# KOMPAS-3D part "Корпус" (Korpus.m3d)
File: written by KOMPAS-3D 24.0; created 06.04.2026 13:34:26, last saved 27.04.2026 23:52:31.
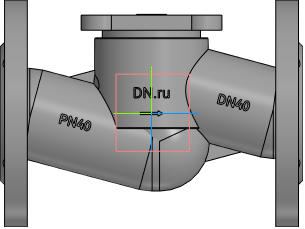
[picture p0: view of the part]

Document properties: Автор: R2D2; Полное имя файла: C:\Работа\ГОТОВЫЕ ИСХОДНИКИ\VSO2130M-F-S Клапан запорный сальниковый DN.ru Ду15-100 Ру40\исходные материалы\DN40\Korpus.m3d

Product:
- Body: Труба / Нестандартная труба / L = 128.1 мм  | qty 1  | 2 such rows
    Материал: Нестандартная труба (density 7856 kg/m3)
    Масса: 9.898009
    Раздел спецификации: Детали
    Примечание: 2,84 кг
    additional columns: Pipeline; 0.06; 0; 0; 0.002; 0.12807; true; 0.04
- Body: Тело 4  | qty 1
    Материал: Нестандартная труба (density 7856 kg/m3)
    Масса: 9.898009
- Body: Тело 5  | qty 1
    Материал: Нестандартная труба (density 7856 kg/m3)
    Масса: 9.898009
- Body: Тело 8  | qty 1
    Материал: Нестандартная труба (density 7856 kg/m3)
    Масса: 9.898009
- Body: Тело 10  | qty 1
    Материал: Нестандартная труба (density 7856 kg/m3)
    Масса: 9.898009
- Body: Тело 11  | qty 1
    Материал: Нестандартная труба (density 7856 kg/m3)
    Масса: 9.898009
- Body: Тело 12  | qty 1
    Материал: Нестандартная труба (density 7856 kg/m3)
    Масса: 9.898009
- Body: Тело 13  | qty 1
    Материал: Нестандартная труба (density 7856 kg/m3)
    Масса: 9.898009
- Part/product: Корпус
    Масса: 6.9

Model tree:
1. Труба:1  (labels: {F703FF30-5BE6-4673-A7F1-8EDA1BE1E2D1}; SHAPEOBJECT3D_ATTR_BUTT; SHAPEOBJECT3D_ATTR_VALID; SHAPEOBJECT3D_ATTR_BUTT_AREA)
     PIPE_R = 3
2. Труба:2  (labels: {F703FF30-5BE6-4673-A7F1-8EDA1BE1E2D1}; SHAPEOBJECT3D_ATTR_BUTT; SHAPEOBJECT3D_ATTR_VALID; SHAPEOBJECT3D_ATTR_BUTT_AREA)
     PIPE_R = 3
3. Колонна
4. Элемент выдавливания:1
     Смещение 1 = -1; Смещение 2 = -5
5. Скругление:17  (with: Ребро.Элемент выдавливания:1)
     Радиус = 0.6
6. Скругление:18  (with: Ребро.Элемент выдавливания:1)
7. Скругление:24
     Радиус = 1.5
8. Элемент выдавливания:2
     Расстояние 1 = 6
9. Эскиз:4  (with: Грань.Элемент выдавливания:1)
10. Элемент выдавливания:3
     Расстояние 1 = 5
11. ОТЛИВКА
12. Скругление:6  (with: Грань.Элемент выдавливания:1)
     Радиус = 2
13. Элемент выдавливания:6  (with: Грань.Элемент выдавливания:1)
     Смещение 1 = 4
14. ЛЕЙБЛ
15. Элемент выдавливания:7  (with: Грань.Элемент выдавливания:1)
     Расстояние 1 = 38.4753; Смещение 1 = 1
16. Dn
17. Pn
18. Стрелочка
19. Элемент выдавливания:10  (with: Грань.Труба:1)
     Расстояние 1 = 30.999; Смещение 1 = 1
20. Элемент выдавливания:11  (with: Грань.Труба:2)
     Расстояние 1 = 30.9306; Смещение 1 = 1
21. Элемент выдавливания:12  (with: Грань.Элемент выдавливания:1)
     Расстояние 1 = 38.4998; Смещение 1 = 1
22. Материал
23. Элемент выдавливания:13  (with: Грань.Элемент выдавливания:1)
     Расстояние 1 = 37.9932; Смещение 1 = 0.5
24. Фланец верх  (with: Грань.Элемент выдавливания:3)
25. Элемент выдавливания:14
     Расстояние 1 = 10
26. Эскиз:18  (with: Грань.Элемент выдавливания:14)
27. Элемент выдавливания:15
     Расстояние 1 = 0.5
28. Эскиз:19  (with: Грань.Элемент выдавливания:14, Ребро.Элемент выдавливания:14)
29. Элемент выдавливания:16  (with: Грань.Элемент выдавливания:14)
     Расстояние 1 = 0.5; Расстояние 2 = 11; Смещение 2 = 1
30. Фланец
31. Элемент вращения:1
     Угол 1 = 360
32. отвертие во фланце  (with: Грань.Элемент вращения:1)
33. Элемент выдавливания:8
34. Массив по концентрической сетке:2  (with: Элемент выдавливания:8, Эскиз:10, Грань.Элемент вращения:1)  (4 pattern instances)
     Шаг 2 = 360
35. Зеркальный массив:1
36. Экземпляр ( 1 )
37. Экземпляр ( 2 )  (with: Элемент вращения:1, Массив по концентрической сетке:2, Экземпляр ( 1 ), Элемент выдавливания:8)
38. Экземпляр ( 3 )  (with: Элемент выдавливания:8)
39. Экземпляр ( 4 )  (with: Элемент выдавливания:8)
40. Скругление:25  (with: Ребро.Элемент выдавливания:1)
     Радиус = 0.6
41. Массив по концентрической сетке:3  (with: Элемент выдавливания:16, Эскиз:19)  (labels: Клапан запорный DN.ru Ду40 Ру40)  (4 pattern instances)
     Шаг 2 = 360

Expressions: DS/2+3; DN/2; LL/2; D1/2; D2/2-10
Referenced files in C:\Работа\ГОТОВЫЕ ИСХОДНИКИ\VSO2130M-F-S Клапан запорный сальниковый DN.ru Ду15-100 Ру40\исходные материалы\DN40\: VSO2130M-F-S Клапан запорный DN.ru Ду40 Ру40.a3d
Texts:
  GOST 26.020 Pr3
  var3D
  GS-C25
  смещение колонны вниз
  LL-10
  DN+20
  DS+10
  Труба / Нестандартная труба / L = %s мм
  Ось Y.Начало координат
